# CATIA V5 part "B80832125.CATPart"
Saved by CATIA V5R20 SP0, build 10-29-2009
Part number: B80832125
Revision: 3
Definition: design
Nomenclature: B80832125
Source: made
Description: NOT SPECIFIED
Bounding box of the stored display mesh (mm): x -18.312 to 18.312, y -18.5 to 18.5, z 0 to 125
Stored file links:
  C:\Users\Raffaele\Desktop\3D X SITO CF\BOLEX\4-PILLAR REF 808\B80832125.CATPart
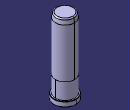
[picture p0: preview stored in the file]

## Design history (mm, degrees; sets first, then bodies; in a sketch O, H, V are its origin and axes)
Body1 "MANIFOLD_SOLID_BREP #450" (main body)
  Solid1: solid without history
